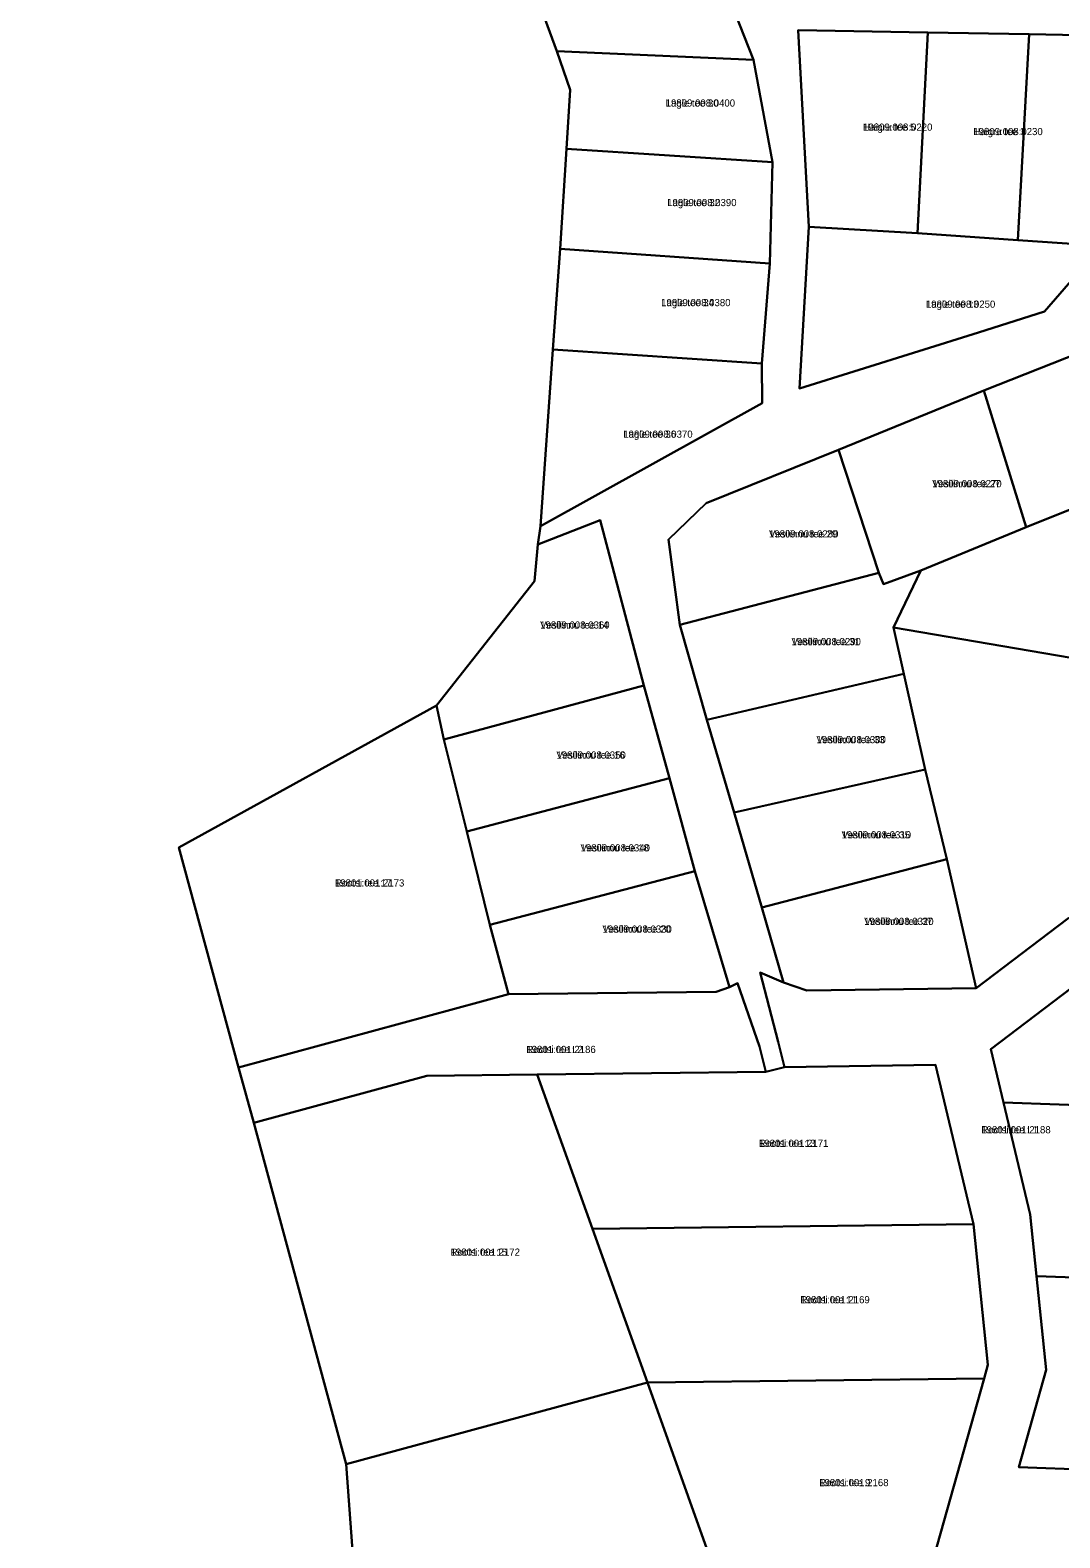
# Model space of a CAD drawing. Extents: x 516875 to 535633, y 6574491 to 6593094.
# Drawn here: x 520086.3 to 520301.5, y 6589156.4 to 6589471.4 of the extents above; entities that cross this region are included whole.
import ezdxf

# ---------------------------------------------------------------- set-up
doc = ezdxf.new("R2010")
doc.units = 0
for name, color, linetype in [('L_AADRESS', 7, 'Continuous'), ('PIIR', 7, 'Continuous'), ('TUNNUS', 7, 'Continuous')]:
    doc.layers.add(name, color=color, linetype=linetype)

msp = doc.modelspace()

# ---------------------------------------------------------------- linework, layer by layer
at = {"layer": 'PIIR'}
for points in [[(519893.32, 6589514.43), (520186.42, 6589533.28), (520184.89, 6589510.34), (520184.56, 6589499.67), (520188.48, 6589488.47), (520196.34, 6589467.05), (520199.19, 6589458.96), (520198.42, 6589446.63), (520197.1, 6589425.75), (520195.51, 6589404.69), (520192.94, 6589367.8), (520192.41, 6589363.94), (520191.69, 6589356.31), (520171.22, 6589330.29), (520117.41, 6589300.67), (520129.88, 6589254.7), (520133.03, 6589243.12), (520152.38, 6589171.78), (520157.47, 6589101.66)], [(520311.53, 6589406.34), (520285.58, 6589396.14), (520255.25, 6589383.7), (520227.61, 6589372.58), (520219.69, 6589364.98), (520222.07, 6589347.15), (520227.69, 6589327.3), (520233.4, 6589307.95), (520239.19, 6589288.12), (520243.74, 6589272.4), (520238.88, 6589274.5), (520242.63, 6589260.02), (520243.97, 6589254.77), (520240.06, 6589253.79), (520238.72, 6589259.03), (520234.11, 6589272.28), (520232.43, 6589271.46), (520225.21, 6589295.71), (520219.93, 6589315.15), (520214.56, 6589334.46), (520205.44, 6589369.04), (520192.41, 6589363.94), (520192.94, 6589367.8), (520239.31, 6589393.46), (520239.2, 6589401.74), (520240.85, 6589422.65), (520241.46, 6589443.83), (520237.44, 6589465.21), (520228.78, 6589487.38)], [(520272.97, 6589144.67), (520285.66, 6589189.73), (520286.46, 6589192.57), (520283.43, 6589221.97), (520275.49, 6589255.2), (520243.97, 6589254.77), (520242.63, 6589260.02), (520238.88, 6589274.5), (520243.74, 6589272.4), (520248.6, 6589270.75), (520283.99, 6589271.23), (520303.07, 6589285.75)], [(520309.35, 6589275.45), (520287.04, 6589258.47), (520289.71, 6589247.33), (520295.29, 6589223.99), (520296.62, 6589211.07), (520298.63, 6589191.52), (520292.9, 6589171.17), (520308.05, 6589170.64)]]:
    msp.add_lwpolyline(points, dxfattribs=at)
for points in [[(520188.48, 6589488.47), (520228.78, 6589487.38), (520237.44, 6589465.21), (520196.34, 6589467.05)], [(520246.83, 6589471.38), (520273.9, 6589470.95), (520271.71, 6589428.99), (520249, 6589430.3)], [(520273.9, 6589470.95), (520246.83, 6589471.38), (520249, 6589430.3), (520247.07, 6589396.51), (520284.52, 6589408.25), (520298.27, 6589412.61), (520310.16, 6589426.33), (520330.04, 6589469.85), (520295.11, 6589470.58)], [(520295.11, 6589470.58), (520292.7, 6589427.54), (520271.71, 6589428.99), (520273.9, 6589470.95)], [(520295.11, 6589470.58), (520330.04, 6589469.85), (520310.16, 6589426.33), (520292.7, 6589427.54)], [(520199.19, 6589458.96), (520196.34, 6589467.05), (520237.44, 6589465.21), (520241.46, 6589443.83), (520198.42, 6589446.63)], [(520198.42, 6589446.63), (520241.46, 6589443.83), (520240.85, 6589422.65), (520197.1, 6589425.75)], [(520249, 6589430.3), (520271.71, 6589428.99), (520292.7, 6589427.54), (520310.16, 6589426.33), (520298.27, 6589412.61), (520284.52, 6589408.25), (520247.07, 6589396.51)], [(520197.1, 6589425.75), (520240.85, 6589422.65), (520239.2, 6589401.74), (520195.51, 6589404.69)], [(520195.51, 6589404.69), (520239.2, 6589401.74), (520239.31, 6589393.46), (520192.94, 6589367.8)], [(520285.58, 6589396.14), (520311.53, 6589406.34), (520342.96, 6589386.97), (520294.44, 6589367.55)], [(520264.61, 6589355.68), (520263.69, 6589358.02), (520255.25, 6589383.7), (520285.58, 6589396.14), (520294.44, 6589367.55), (520272.44, 6589358.51)], [(520347.45, 6589388.79), (520359.75, 6589381.2), (520351.44, 6589340.31), (520350.92, 6589333.49), (520346.28, 6589333), (520266.75, 6589346.61), (520272.44, 6589358.51), (520294.44, 6589367.55), (520342.96, 6589386.97)], [(520219.69, 6589364.98), (520227.61, 6589372.58), (520255.25, 6589383.7), (520263.69, 6589358.02), (520222.07, 6589347.15)], [(520171.22, 6589330.29), (520191.69, 6589356.31), (520192.41, 6589363.94), (520205.44, 6589369.04), (520214.56, 6589334.46), (520172.79, 6589323.21)], [(520222.07, 6589347.15), (520263.69, 6589358.02), (520264.61, 6589355.68), (520272.44, 6589358.51), (520266.75, 6589346.61), (520268.86, 6589336.91), (520227.69, 6589327.3)], [(520266.75, 6589346.61), (520346.28, 6589333), (520322.95, 6589295.24), (520303.07, 6589285.75), (520283.99, 6589271.23), (520277.85, 6589298.17), (520273.36, 6589316.96), (520268.86, 6589336.91)], [(520172.79, 6589323.21), (520214.56, 6589334.46), (520219.93, 6589315.15), (520177.55, 6589303.96)], [(520227.69, 6589327.3), (520268.86, 6589336.91), (520273.36, 6589316.96), (520233.4, 6589307.95)], [(520171.22, 6589330.29), (520172.79, 6589323.21), (520177.55, 6589303.96), (520182.35, 6589284.49), (520186.24, 6589269.99), (520129.88, 6589254.7), (520117.41, 6589300.67)], [(520233.4, 6589307.95), (520273.36, 6589316.96), (520277.85, 6589298.17), (520239.19, 6589288.12)], [(520177.55, 6589303.96), (520219.93, 6589315.15), (520225.21, 6589295.71), (520182.35, 6589284.49)], [(520345.63, 6589301.5), (520361.2, 6589301.06), (520359.48, 6589244.87), (520289.71, 6589247.33), (520287.04, 6589258.47), (520309.35, 6589275.45), (520337.98, 6589289.11)], [(520243.74, 6589272.4), (520239.19, 6589288.12), (520277.85, 6589298.17), (520283.99, 6589271.23), (520248.6, 6589270.75)], [(520182.35, 6589284.49), (520225.21, 6589295.71), (520232.43, 6589271.46), (520229.67, 6589270.51), (520186.24, 6589269.99)], [(520234.11, 6589272.28), (520238.72, 6589259.03), (520240.06, 6589253.79), (520192.25, 6589253.22), (520169.23, 6589252.94), (520133.03, 6589243.12), (520129.88, 6589254.7), (520186.24, 6589269.99), (520229.67, 6589270.51), (520232.43, 6589271.46)], [(520192.25, 6589253.22), (520203.8, 6589220.98), (520215.31, 6589188.86), (520152.38, 6589171.78), (520133.03, 6589243.12), (520169.23, 6589252.94)], [(520192.25, 6589253.22), (520240.06, 6589253.79), (520243.97, 6589254.77), (520275.49, 6589255.2), (520283.43, 6589221.97), (520203.8, 6589220.98)], [(520359.48, 6589244.87), (520358.38, 6589208.89), (520296.62, 6589211.07), (520295.29, 6589223.99), (520289.71, 6589247.33)], [(520283.43, 6589221.97), (520286.46, 6589192.57), (520285.66, 6589189.73), (520215.31, 6589188.86), (520203.8, 6589220.98)], [(520358.38, 6589208.89), (520357.84, 6589191.11), (520363.84, 6589190.92), (520363.06, 6589168.7), (520308.05, 6589170.64), (520292.9, 6589171.17), (520298.63, 6589191.52), (520296.62, 6589211.07)], [(520285.66, 6589189.73), (520272.97, 6589144.67), (520228.1, 6589153.14), (520215.31, 6589188.86)], [(520215.31, 6589188.86), (520228.1, 6589153.14), (520226.22, 6589143.18), (520231.62, 6589143.32), (520231.33, 6589102.32), (520157.47, 6589101.66), (520152.38, 6589171.78)]]:
    msp.add_lwpolyline(points, close=True, dxfattribs=at)

# ---------------------------------------------------------------- texts
at = {"layer": 'L_AADRESS'}
for s, p in [('Lagle tee 30', (520219.12, 6589455.44)), ('Haigru tee 5', (520260.36, 6589450.4)), ('Haigru tee 3', (520283.41, 6589449.48)), ('Lagle tee 32', (520219.43, 6589434.64)), ('Lagle tee 34', (520218.17, 6589413.74)), ('Lagle tee 13', (520273.5, 6589413.41)), ('Lagle tee 36', (520210.25, 6589386.25)), ('Vesilinnu tee 27', (520274.83, 6589375.91)), ('Vesilinnu tee 29', (520240.71, 6589365.42)), ('Vesilinnu tee 14', (520192.89, 6589346.38)), ('Vesilinnu tee 31', (520245.41, 6589342.91)), ('Vesilinnu tee 33', (520250.63, 6589322.43)), ('Vesilinnu tee 16', (520196.29, 6589319.21)), ('Vesilinnu tee 35', (520255.89, 6589302.54)), ('Vesilinnu tee 18', (520201.33, 6589299.82)), ('Rootsi tee 17', (520150, 6589292.49)), ('Vesilinnu tee 20', (520205.91, 6589282.85)), ('Vesilinnu tee 37', (520260.61, 6589284.46)), ('Rootsi tee L2', (520190, 6589257.7)), ('Rootsi tee L1', (520285.07, 6589240.92)), ('Rootsi tee 13', (520238.62, 6589238.09)), ('Rootsi tee 15', (520174.17, 6589215.35)), ('Rootsi tee 11', (520247.26, 6589205.41)), ('Rootsi tee 9', (520251.19, 6589167.2))]:
    msp.add_text(s, height=1.5, dxfattribs=at).set_placement(p)
at = {"layer": 'TUNNUS'}
for s, p in [('19809:008:0400', (520219.12, 6589455.44)), ('19809:008:0220', (520260.36, 6589450.4)), ('19809:008:0230', (520283.41, 6589449.48)), ('19809:008:0390', (520219.43, 6589434.64)), ('19809:008:0380', (520218.17, 6589413.74)), ('19809:008:0250', (520273.5, 6589413.41)), ('19809:008:0370', (520210.25, 6589386.25)), ('19809:008:0270', (520274.83, 6589375.91)), ('19809:008:0280', (520240.71, 6589365.42)), ('19809:008:0360', (520192.89, 6589346.38)), ('19809:008:0290', (520245.41, 6589342.91)), ('19809:008:0300', (520250.63, 6589322.43)), ('19809:008:0350', (520196.29, 6589319.21)), ('19809:008:0310', (520255.89, 6589302.54)), ('19809:008:0340', (520201.33, 6589299.82)), ('19801:001:2173', (520150, 6589292.49)), ('19809:008:0330', (520205.91, 6589282.85)), ('19809:008:0320', (520260.61, 6589284.46)), ('19801:001:2186', (520190, 6589257.7)), ('19801:001:2188', (520285.07, 6589240.92)), ('19801:001:2171', (520238.62, 6589238.09)), ('19801:001:2172', (520174.17, 6589215.35)), ('19801:001:2169', (520247.26, 6589205.41)), ('19801:001:2168', (520251.19, 6589167.2))]:
    msp.add_text(s, height=1.5, dxfattribs=at).set_placement(p)

doc.saveas('drawing.dxf')
